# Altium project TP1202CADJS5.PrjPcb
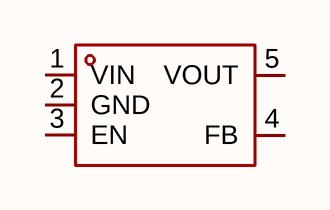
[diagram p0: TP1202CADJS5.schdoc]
1 sheet, 1 parts. Net scope: global (net labels, ports and power ports of the same name join across sheets).

## Sheet TP1202CADJS5.schdoc
size 127 x 101 mm

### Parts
U?  tp1202cadjs5  [SOT-23-5_L2.9-W1.6-P0.95-LS2.8-BR]  (value not drawn)

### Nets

Not connected (* = marked no-connect by the designer): U? 1(VIN) 2(GND) 3(EN) 4(FB) 5(VOUT)

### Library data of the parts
U? = tp1202cadjs5: 输出极性:正极;工作电压:100V;输出电流:50mA;电源纹波抑制比(PSRR):-;输出类型:可调;; Manufacturer: TECH PUBLIC(台舟); AddInBom: yes; ModelId: 7ba65df16e7b4570af156e925f9c37fe; ModelTransform: 114.173,114.173,0,90,0,0,0,0,0; Output Configuration: 正极; Voltage - Supply: 100V; Output Current: 50mA; Voltage Dropout: 2.8V@(50mA); standby current: 23uA; Output Type: 可调; Number of Outputs: 1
